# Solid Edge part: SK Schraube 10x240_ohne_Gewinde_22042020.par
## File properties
Author: fknapp
Template: Normal.par
Last saved by: fknapp
Revision: 22
Application: Solid Edge
Username: fknapp
Material: Aluminium
Genauigkeit: 0,99
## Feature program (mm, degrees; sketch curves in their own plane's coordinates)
sketch for "unnamed RevolvedProtrusion 1" plane through (0, 0, 0) normal (0, 0, 1) x-axis (1, 0, 0)
  line (0, 54) -> (9, 54)
  line (9, 54) -> (9, 53)
  line (9, 53) -> (5, 49)
  line (5, 49) -> (5, 46.3)
  line (5, 46.3) -> (4.7548, 46.3)
  arc centre (4.7548, 44.6952) radius 1.6048 from (4.7548, 46.3) to (3.15, 44.6952) ccw
  line (3.15, 44.6952) -> (3.15, 42)
  line (3.15, 42) -> (5, 42)
  line (5, -173) -> (5, 42)
  line (0.5, -186) -> (5, -173)
  line (0, -186) -> (0.5, -186)
revolve "unnamed RevolvedProtrusion 1" add full turn 360 deg about sketch line (0, 54) -> (0, -186)
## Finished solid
Body 1: solid body, 11 faces, 10 edges, 0 vertices.
  Faces by surface: cylinder 4, plane 4, cone 2, torus 1
  Edges by curve: circle 10
Bounding box of the edges (mm; curved faces can reach further): 18.000 x 240.000 x 18.000, from (-9, -186, -9) to (9, 54, 9).
Cylindrical faces by radius (mm): R3.15 x1, R5 x2, R9 x1
Conical faces (half-angle, radius in mm at the cone's reference point): 19.0935 deg R5 x1, 45 deg R9 x1
Toroidal faces (ring radius, tube radius in mm): R4.7548 r1.6048 x1
Planar faces by outward normal: +y 2, -y 2
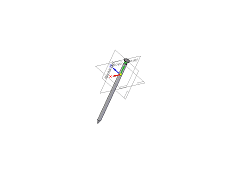
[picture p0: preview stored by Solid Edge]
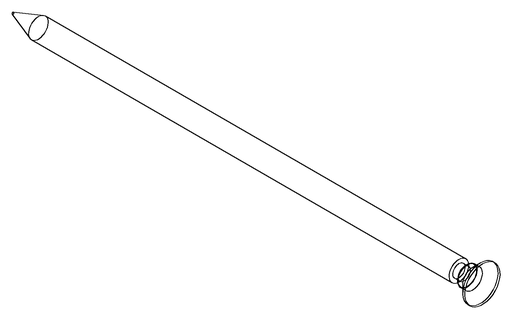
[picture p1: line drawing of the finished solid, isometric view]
